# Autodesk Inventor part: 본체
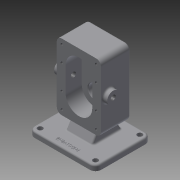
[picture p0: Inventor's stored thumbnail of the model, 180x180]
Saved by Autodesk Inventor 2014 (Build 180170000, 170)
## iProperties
Created: 2020-04
Part Number: 본체
Material: Generic
Document SubType Name: Modeling
Designer: kh
Density: 1 g/cm^3
Appearance: Default
Mass: 544.869 g
Surface Area: 819.61 cm^2
Volume: 544.869 cm^3
Author: kh
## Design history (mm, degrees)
sketch "스케치1"
  geometry: L1 (-50, 60)-(50, 60); L2 (50, 60)-(50, -60); L3 (50, -60)-(-50, -60); L4 (-50, -60)-(-50, 60); L5 (-50, 60)-(50, -60); L6 (50, 60)-(-50, -60); 3 further points
  constraints: 12 end point, 3 midpoint, 2 parallel, 1 coincident, 1 horizontal, 1 perpendicular
  dimensions: "d0" = 100 distance of L1.start L1.end; "d1" = 120 distance of L3.end L1.start
extrude "돌출1" new body sketch "스케치1" distance "d2" = 10; taper "d3" = 0 deg
node "작업 평면1"
sketch "스케치2"
  geometry: L1 (0, 0)-(0, 120) reference; L2 (0, 0)-(-10, 0) reference; L3 (-10, 120)-(-10, 0) reference; L4 (0, 120)-(-10, 120) reference; L5 (-150, 20)-(-30, 20); L6 (-30, 20)-(-30, 100); L7 (-30, 100)-(-150, 100); L8 (-150, 100)-(-150, 20); L9 (-150, 20)-(-30, 100); L10 (-30, 20)-(-150, 100); 4 further points
  constraints: 12 end point, 4 midpoint, 2 parallel, 1 horizontal, 1 horizontal alignment, 1 perpendicular
  dimensions: "d5" = 80 distance of L7.end L5.start; "d6" = 150 distance between parallel lines of L8 L1; "d7" = 120 distance between parallel lines of L6 L8
extrude "돌출2" join sketch "스케치2" distance "d8" = 53; taper "d9" = 0 deg
sketch "스케치3"
  geometry: L1 (30, 20)-(150, 20) reference; L2 (150, 20)-(150, 100) reference; L3 (150, 100)-(30, 100) reference; L4 (30, 100)-(30, 20) reference; L5 (0, 0)-(0, 120) reference; L6 (0, 0)-(10, 0) reference; L7 (10, 120)-(10, 0) reference; L8 (0, 120)-(10, 120) reference; L9 (68, 60)-(112, 60); L10 (68, 84)-(112, 84); L11 (112, 36)-(68, 36); A1 r 24 centre (68, 60) between (68, 84) and (68, 36); A2 r 24 centre (112, 60) between (112, 36) and (112, 84); 3 further points
  constraints: 8 end point, 4 point on circle, 4 tangent, 2 centre point, 2 midpoint, 2 parallel, 1 horizontal alignment
  dimensions: "d10" = 24 radius of A2; "d11" = 44 distance of L9.start L9.end; "d12" = 90 distance of point (90, 60) point (0, 60)
extrude "돌출3" cut sketch "스케치3" distance "d13" = 29; taper "d14" = 0 deg
sketch "스케치4"
  geometry: L1 (68, 84)-(112, 84) reference; L2 (112, 36)-(68, 36) reference; A1 r 24 centre (68, 60) between (68, 84) and (68, 36) reference; A2 r 24 centre (112, 60) between (112, 36) and (112, 84) reference; 3 further points
  constraints: 2 coincident
hole "구멍1" sketch "스케치4" at (112, 60), (68, 60) diameter "d15" = 25; stored, may be unused: countersink angle "d19" = 90 deg, drill point angle "d21" = 0 deg; dims "d16" = 6, "d17" = 4, "d18" = 2, "d20" = 15
sketch "스케치5"
  geometry: C1 r 12.5 at (-112, 60) reference; C2 r 19 at (-112, 60); 1 further point
  constraints: 1 centre point, 1 coincident
  dimensions: "d22" = 38 diameter of C2
extrude "돌출4" join sketch "스케치5" distance "d23" = 17; taper "d24" = 0 deg
hole "구멍2" diameter "d27" = 17; stored, may be unused: countersink angle "d31" = 90 deg, drill point angle "d33" = 0 deg; dims "d25" = 10, "d26" = 10, "d28" = 6, "d29" = 28, "d30" = 7.3, "d32" = 15
sketch "스케치6"
  geometry: L1 (17, -30)-(-83, -30) reference; L2 (-53, 0)-(-53, 120) reference; C1 r 11 at (-39, 60); 1 further point
  constraints: 1 centre point
  dimensions: "d34" = 22 diameter of C1; "d35" = 90 distance from line of L1 C1.centre; "d36" = 14 distance from line of L2 C1.centre
extrude "돌출5" join sketch "스케치6" distance "d37" = 8; taper "d38" = 0 deg
hole "구멍3" diameter "d41" = 8.917; stored, may be unused: countersink angle "d45" = 90 deg, drill point angle "d47" = 0 deg; dims "d39" = 10, "d40" = 10, "d42" = 6, "d43" = 28, "d44" = 7.3, "d46" = 15
sketch "스케치7"
  geometry: L1 (68, 84)-(112, 84) reference; L2 (112, 36)-(68, 36) reference; L3 (30, 20)-(150, 20) reference; L4 (150, 20)-(150, 100) reference; L5 (150, 100)-(30, 100) reference; L6 (30, 100)-(30, 20) reference; L7 (141, 91)-(39, 91); L8 (39, 91)-(39, 29); L9 (39, 29)-(141, 29); L10 (141, 29)-(141, 91); L11 (141, 91)-(39, 29); L12 (39, 91)-(141, 29); L13 (0, 0)-(0, 120) reference; L14 (112, 91)-(112, 29); L15 (68, 91)-(68, 29); A1 r 24 centre (68, 60) between (68, 84) and (68, 36) reference; A2 r 24 centre (112, 60) between (112, 36) and (112, 84) reference; 12 further points
  constraints: 16 end point, 8 coincident, 4 midpoint, 4 point on line, 3 perpendicular, 2 parallel, 1 horizontal, 1 horizontal alignment
  dimensions: "d48" = 62 distance of L9.end L7.start; "d49" = 90 distance from line of point (90, 60) L13; "d50" = 102 distance of L8.end L9.end; "d51" = 29 distance between parallel lines of L14 L10; "d52" = 44 distance from line of L15 L2.start
hole "구멍4" sketch "스케치7" at (141, 91), (112, 91), (68, 91), (39, 91), (39, 29), (68, 29), (112, 29), (141, 29) diameter "d53" = 4.459; stored, may be unused: countersink angle "d57" = 90 deg, drill point angle "d59" = 118 deg; dims "d54" = 10, "d55" = 28, "d56" = 7.3, "d58" = 12
sketch "스케치8"
  geometry: L1 (50, 10)-(50, 0) reference; L2 (50, 0)-(-50, 0) reference; L3 (-50, 0)-(-50, 10) reference; L4 (-50, 10)-(50, 10) reference; L5 (20, 30)-(-33, 30) reference; L6 (-33, 30)-(-33, 93) reference; L7 (-33, 93)-(-50, 93) reference; L8 (-50, 93)-(-50, 98) reference; L9 (-50, 98)-(-42.7, 98) reference; L10 (-42.7, 98)-(-42.7, 103.5) reference; L11 (-42.7, 103.5)-(-24, 103.5) reference; L12 (-24, 103.5)-(-24, 99.5) reference; L13 (-24, 99.5)-(-9, 99.5) reference; L14 (-9, 99.5)-(-9, 80.5) reference; L15 (-9, 80.5)-(-24, 80.5) reference; L16 (-24, 80.5)-(-24, 55.5) reference; L17 (-24, 55.5)-(-9, 55.5) reference; L18 (-9, 55.5)-(-9, 44) reference; L19 (-9, 44)-(20, 44) reference; L20 (20, 44)-(20, 30) reference; L21 (-33, 150)-(20, 150) reference; L22 (20, 150)-(20, 136) reference; L23 (20, 136)-(-9, 136) reference; L24 (-9, 136)-(-9, 124.5) reference; L25 (-9, 124.5)-(-24, 124.5) reference; L26 (-24, 124.5)-(-24, 120.5) reference; L27 (-24, 120.5)-(-42.7, 120.5) reference; L28 (-42.7, 120.5)-(-42.7, 126) reference; L29 (-42.7, 126)-(-50, 126) reference; L30 (-50, 126)-(-50, 131) reference; L31 (-50, 131)-(-33, 131) reference; L32 (-33, 131)-(-33, 150) reference; L33 (20, 10)-(8.453, 30); L34 (-33, 10)-(-21.453, 30); L35 (20, 10)-(-33, 10); L36 (8.453, 30)-(-21.453, 30); 1 further point
  constraints: 8 end point, 4 point on line, 2 collinear
  dimensions: "d60" = 17 distance from line of L3 L34.start; "d61" = 60 deg angle of L4 L34; "d62" = 53 distance of L33.start L34.start; "d63" = 60 deg angle of L4 L33
extrude "돌출6" join sketch "스케치8" stored distance "d64" = 48; taper "d65" = 0 deg
fillet "모깎기1" dims "d66" = 10
sketch "스케치9"
  geometry: L1 (40, 60)-(-40, 60) reference; L2 (-50, 50)-(-50, -50) reference; L3 (-40, -60)-(40, -60) reference; L4 (50, -50)-(50, 50) reference; L5 (33, -24)-(-20, -24) reference; L6 (-20, -24)-(-20, 24) reference; L7 (-20, 24)-(33, 24) reference; L8 (33, 24)-(33, -24) reference; A1 r 10 centre (40, 50) between (50, 50) and (40, 60) reference; A2 r 10 centre (-40, 50) between (-40, 60) and (-50, 50) reference; A3 r 10 centre (-40, -50) between (-50, -50) and (-40, -60) reference; A4 r 10 centre (40, -50) between (40, -60) and (50, -50) reference; 5 further points
  constraints: 4 coincident
hole "구멍5" sketch "스케치9" at (-40, 50), (-40, -50), (40, -50), (40, 50) diameter "d67" = 9; stored, may be unused: countersink angle "d71" = 90 deg, drill point angle "d73" = 118 deg; dims "d68" = 10, "d69" = 28, "d70" = 7.3, "d72" = 12
fillet "모깎기2" dims "d74" = 9
fillet "모깎기3" dims "d75" = 3
fillet "모깎기4" dims "d76" = 3
fillet "모깎기5" dims "d77" = 3
chamfer "모따기1" distance "d78" = 0.7; stored, may be unused: second distance "d79" = 2, angle "d80" = 30 deg
fillet "모깎기6" dims "d81" = 0.5
sketch "스케치10"
  geometry: L1 (-37.031, 20.509)-(-37.031, -20.97); L2 (-37.031, -20.97)-(-43.035, -20.97); L3 (-43.035, -20.97)-(-43.035, 20.509); L4 (-43.035, 20.509)-(-37.031, 20.509); L5 (-43.035, -20.97)-(-37.031, 20.509); L6 (-37.031, -20.059)-(-43.035, 20.509); L7 (-50, 50)-(-50, -50) reference; L8 (-40, -60)-(40, -60) reference; 2 further points
  constraints: 4 end point, 3 point on line, 2 other
  dimensions: "d82" = 10 distance from line of L7 point (-40, 0); "d83" = 60 distance from line of L8 point (-40, 0)
feature "엠보싱1" sketch "스케치10" dims "d0" = 100, "d1" = 120, "d84" = 0.5, "d85" = 0
chamfer "모따기2" distance "d86" = 1; stored, may be unused: second distance "d87" = 2, angle "d88" = 45 deg
node "솔리드1"
mirror "대칭1"
node "투영된 루프1"
node "투영된 루프2"
node "투영된 루프3"
node "투영된 루프4"
node "투영된 루프5"
node "투영된 루프6"
node "절단 모서리 투영1"
other parameters: "d4" = -17
